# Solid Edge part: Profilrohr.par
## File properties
Username: bmolnar
Dokumentum tartalom típus: 0
Author: bmolnar
Last saved by: bmolnar
Revision: 77
Sűrűség: 0,000 kg/m^3
Pontosság: 0,990
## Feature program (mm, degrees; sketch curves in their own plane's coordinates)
base feature "unnamed BaseFeature 1"
thread "unnamed Thread 1"
thread "Menet_2"  ThreadDepth = 5.5 mm
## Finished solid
Body 1: solid body, 127 faces, 307 edges, 215 vertices.
  Faces by surface: cylinder 57, plane 52, cone 16, torus 2
  Edges by curve: line 144, circle 142, curve on surface 12, spline 9
Bounding box of the edges (mm; curved faces can reach further): 30.000 x 34.000 x 37.000, from (-15, -15, 0) to (15, 19, 37).
Cylindrical faces by radius (mm): R0.3 x24, R0.65 x2, R1.85 x4, R2 x2, R2.067 x4, R2.35 x2, R2.8 x4, R3.75 x4, R8 x1, R8.95 x2, R9.1 x2, R9.5 x2, R20 x4
Conical faces (half-angle, radius in mm at the cone's reference point): 45 deg R2.317 x2, 45 deg R2.95 x4, 45 deg R3.9 x4, 45 deg R8.4 x2, 45 deg R9.2 x2, 45 deg R9.25 x2
Toroidal faces (ring radius, tube radius in mm): R9.4 r0.1 x2
Planar faces by outward normal: +x 6, +y 9, +z 9, -x 6, -y 5, -z 9, oblique 8
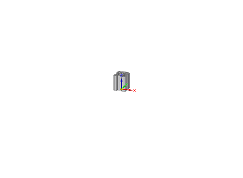
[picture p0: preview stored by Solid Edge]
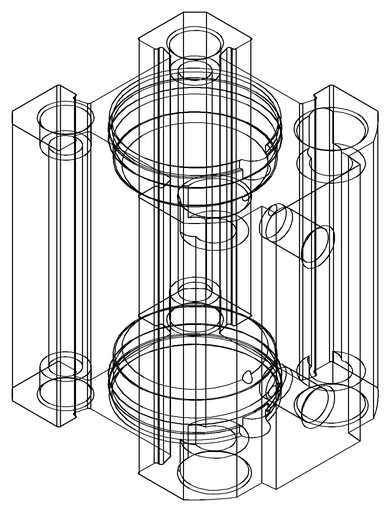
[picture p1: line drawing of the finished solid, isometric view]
